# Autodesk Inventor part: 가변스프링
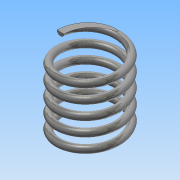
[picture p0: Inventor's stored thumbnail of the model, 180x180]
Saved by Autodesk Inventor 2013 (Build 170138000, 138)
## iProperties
Created: 2016-03
Part Number: 가변스프링
Material: 스테인리스강
Document SubType Name: Modeling
Designer: Administrator
Density: 8.08 g/cm^3
Mass: 6.6379 g
Surface Area: 16.7089 cm^2
Volume: 0.821522 cm^3
Author: Administrator
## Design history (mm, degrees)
sketch "스케치1"
  geometry: L1 (0, 0)-(8.5, 0); L2 (8.5, 20.5)-(0, 20.5); L3 (0, 20.5)-(0, 0); C1 r 1 at (8.5, 0)
  constraints: 6 end point, 2 parallel, 1 centre point, 1 coincident, 1 horizontal, 1 vertical
  dimensions: "d0" = 2 diameter of C1; "d1" = 17 diameter of C1.centre L3; "d2" = 20.5 distance between parallel lines of L1 L2 (derived)
feature "코일1" sketch "스케치1" pitch "d3" = 10; turns "d5" = 5; dims "d4" = 20.5 (= d2), "d6" = 0, angle "d7" = 90 deg, angle "d8" = 90 deg, "d9" = 0, "d10" = 0
sketch "스케치2"
  geometry: L1 (-10, 20.5)-(10, 20.5); L2 (10, 20.5)-(10, 0); L3 (10, 0)-(-10, 0); L4 (-10, 0)-(-10, 20.5); 2 further points
  constraints: 8 end point, 2 parallel, 1 coincident, 1 horizontal, 1 midpoint, 1 perpendicular
  dimensions: "d11" = 20.5 distance between parallel lines of L3 L1 (derived); "d13" = 20 distance of L1.start L1.end
extrude "돌출1" sketch "스케치2" stored distance "d14" = 10; taper "d15" = 0 deg
node "솔리드1"
